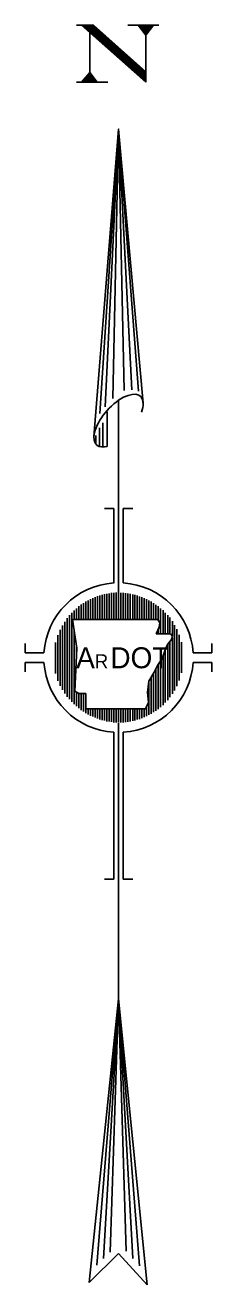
# Model space of a CAD drawing. Extents: x -0.25 to 1.92, y 0 to 0.95.
# Drawn here: x 1.6158 to 1.6401, y 0.2614 to 0.4252 of the extents above; entities that cross this region are included whole.
import ezdxf

# ---------------------------------------------------------------- set-up
doc = ezdxf.new("R2010")
doc.units = 0
doc.layers.add('SHET_Border-Text', color=7, linetype='Continuous')

msp = doc.modelspace()

# ---------------------------------------------------------------- linework, layer by layer
at = {"layer": 'SHET_Border-Text'}
for p, q in [((1.6224669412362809, 0.42522347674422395), (1.6246832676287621, 0.42522347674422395)), ((1.623141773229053, 0.42522347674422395), (1.6314915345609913, 0.41780460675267)), ((1.6232376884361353, 0.42522347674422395), (1.6314915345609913, 0.4179013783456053)), ((1.6233344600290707, 0.42522347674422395), (1.6314915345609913, 0.4179656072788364)), ((1.6234303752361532, 0.42522347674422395), (1.6314915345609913, 0.418061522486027)), ((1.6235271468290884, 0.42522347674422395), (1.6314915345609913, 0.41812575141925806)), ((1.623623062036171, 0.42522347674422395), (1.6314915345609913, 0.41822252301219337)), ((1.6236872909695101, 0.42522347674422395), (1.6314915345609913, 0.4182867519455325)), ((1.623784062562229, 0.42522347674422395), (1.6314915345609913, 0.418382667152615)), ((1.6238799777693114, 0.42522347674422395), (1.6314915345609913, 0.4184468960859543)), ((1.6239767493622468, 0.42522347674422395), (1.6314915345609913, 0.41854366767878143)), ((1.6240726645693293, 0.42522347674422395), (1.6314915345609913, 0.4186395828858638)), ((1.6241694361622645, 0.42522347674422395), (1.6314915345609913, 0.4187038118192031)), ((1.6242011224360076, 0.42522347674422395), (1.6242011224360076, 0.41780460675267)), ((1.624265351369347, 0.42522347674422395), (1.6314915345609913, 0.4188005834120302)), ((1.6243295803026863, 0.42522347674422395), (1.6314915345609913, 0.4188648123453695)), ((1.6244263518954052, 0.42522347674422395), (1.6314915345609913, 0.41896072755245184)), ((1.6245222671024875, 0.42522347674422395), (1.6314915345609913, 0.41902495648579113)), ((1.6246190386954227, 0.42522347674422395), (1.6314915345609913, 0.41912172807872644)), ((1.6246832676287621, 0.42522347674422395), (1.6314915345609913, 0.4191534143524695)), ((1.6310093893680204, 0.42522347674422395), (1.6291467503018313, 0.42522347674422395)), ((1.6331931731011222, 0.42522347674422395), (1.6310093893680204, 0.42522347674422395)), ((1.6314915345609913, 0.42522347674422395), (1.6314915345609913, 0.41780460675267)), ((1.6224669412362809, 0.41780460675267), (1.6246832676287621, 0.41780460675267)), ((1.6246832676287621, 0.41780460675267), (1.6265459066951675, 0.41780460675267)), ((1.6279589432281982, 0.351488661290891), (1.6279589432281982, 0.37640948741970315)), ((1.6259036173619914, 0.3704361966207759), (1.6259036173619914, 0.3735191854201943)), ((1.6264816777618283, 0.3704361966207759), (1.6264816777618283, 0.37496390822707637)), ((1.6249718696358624, 0.3709174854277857), (1.6249718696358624, 0.37188091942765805)), ((1.6254540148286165, 0.3705321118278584), (1.6254540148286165, 0.37284435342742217)), ((1.626127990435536, 0.3623750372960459), (1.6273483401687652, 0.3623750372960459)), ((1.6273483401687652, 0.35267646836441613), (1.6273483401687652, 0.3623750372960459)), ((1.6285686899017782, 0.3527090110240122), (1.6285686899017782, 0.3623750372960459)), ((1.6285686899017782, 0.3623750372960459), (1.6297890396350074, 0.3623750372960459)), ((1.624297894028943, 0.34795606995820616), (1.624297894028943, 0.35058945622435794)), ((1.6246190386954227, 0.34795606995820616), (1.6246190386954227, 0.3507179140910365)), ((1.624907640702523, 0.34795606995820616), (1.624907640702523, 0.35084637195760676)), ((1.6251970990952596, 0.34795606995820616), (1.6251970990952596, 0.35097482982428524)), ((1.6255182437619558, 0.34795606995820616), (1.6255182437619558, 0.3510707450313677)), ((1.625806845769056, 0.34795606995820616), (1.625806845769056, 0.3511675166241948)), ((1.626127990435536, 0.34795606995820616), (1.626127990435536, 0.35123174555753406)), ((1.6264174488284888, 0.34795606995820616), (1.6264174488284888, 0.3512959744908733)), ((1.6267385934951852, 0.34795606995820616), (1.6267385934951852, 0.3513276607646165)), ((1.627027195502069, 0.34795606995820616), (1.627027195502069, 0.35139188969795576)), ((1.6273483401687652, 0.34795606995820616), (1.6273483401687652, 0.3514244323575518)), ((1.627637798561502, 0.34795606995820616), (1.627637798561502, 0.351456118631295)), ((1.6279589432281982, 0.34795606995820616), (1.6279589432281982, 0.351488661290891)), ((1.6282475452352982, 0.34795606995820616), (1.6282475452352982, 0.3514244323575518)), ((1.6285686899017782, 0.34795606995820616), (1.6285686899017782, 0.3514244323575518)), ((1.6288581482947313, 0.34795606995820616), (1.6288581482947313, 0.35136020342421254)), ((1.6291792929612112, 0.34795606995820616), (1.6291792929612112, 0.3513276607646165)), ((1.6294678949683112, 0.34795606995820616), (1.6294678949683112, 0.3512634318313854)), ((1.6297890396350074, 0.34795606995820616), (1.6297890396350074, 0.3511992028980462)), ((1.6300784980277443, 0.34795606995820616), (1.6300784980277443, 0.35113497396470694)), ((1.6303671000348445, 0.34795606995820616), (1.6303671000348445, 0.3510390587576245)), ((1.6306882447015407, 0.34795606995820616), (1.6306882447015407, 0.35094228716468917)), ((1.6309777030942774, 0.34795606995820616), (1.6309777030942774, 0.35084637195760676)), ((1.6312988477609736, 0.34795606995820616), (1.6312988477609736, 0.3507179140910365)), ((1.6315874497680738, 0.34795606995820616), (1.6315874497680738, 0.35058945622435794)), ((1.6221783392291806, 0.34795606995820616), (1.6221783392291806, 0.349112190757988)), ((1.6224669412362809, 0.34795606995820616), (1.6224669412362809, 0.3493691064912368)), ((1.622788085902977, 0.34795606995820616), (1.622788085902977, 0.349657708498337)), ((1.6230775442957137, 0.34795606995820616), (1.6230775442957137, 0.34988293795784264)), ((1.62339868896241, 0.34795606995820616), (1.62339868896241, 0.3500756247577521)), ((1.6236872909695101, 0.34795606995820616), (1.6236872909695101, 0.35026831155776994)), ((1.62400843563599, 0.34795606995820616), (1.62400843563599, 0.35042845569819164)), ((1.6319085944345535, 0.34795606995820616), (1.6319085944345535, 0.35042845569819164)), ((1.6321980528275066, 0.34795606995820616), (1.6321980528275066, 0.35026831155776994)), ((1.6325191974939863, 0.34795606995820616), (1.6325191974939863, 0.3500756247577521)), ((1.6328077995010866, 0.34795606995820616), (1.6328077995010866, 0.3498503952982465)), ((1.633128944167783, 0.3478918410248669), (1.633128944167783, 0.349657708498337)), ((1.6334184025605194, 0.3461251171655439), (1.6334184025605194, 0.3493691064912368)), ((1.6337395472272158, 0.3461251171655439), (1.6337395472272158, 0.3491438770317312)), ((1.6209579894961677, 0.33832172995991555), (1.6209579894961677, 0.34763492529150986)), ((1.6212465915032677, 0.337872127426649), (1.6212465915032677, 0.3481162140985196)), ((1.6215677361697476, 0.33758266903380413), (1.6215677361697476, 0.3485015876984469)), ((1.6218571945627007, 0.33722983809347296), (1.6218571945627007, 0.3487910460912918)), ((1.62253117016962, 0.3442307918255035), (1.621953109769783, 0.34795606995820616)), ((1.621953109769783, 0.34795606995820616), (1.6330647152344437, 0.34795606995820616)), ((1.6330647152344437, 0.34795606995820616), (1.6330647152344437, 0.34795606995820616)), ((1.6330647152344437, 0.34795606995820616), (1.6333216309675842, 0.3475064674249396)), ((1.6333216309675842, 0.3475064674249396), (1.6332574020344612, 0.3469600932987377)), ((1.634028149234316, 0.3461251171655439), (1.634028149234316, 0.34882273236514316)), ((1.6343492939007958, 0.3460934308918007), (1.6343492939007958, 0.3485015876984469)), ((1.6346387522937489, 0.3460934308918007), (1.6346387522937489, 0.34818044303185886)), ((1.6349598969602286, 0.34586820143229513), (1.6349598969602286, 0.3477308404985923)), ((1.6200262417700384, 0.33995913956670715), (1.6200262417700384, 0.34590074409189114)), ((1.6203473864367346, 0.3393168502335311), (1.6203473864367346, 0.3466072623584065)), ((1.6206368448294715, 0.3388030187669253), (1.6206368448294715, 0.3471527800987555)), ((1.6221783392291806, 0.33690869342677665), (1.6221783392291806, 0.3464145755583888)), ((1.6332574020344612, 0.3469600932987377), (1.6328403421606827, 0.3460934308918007)), ((1.6328403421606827, 0.3460934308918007), (1.6347346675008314, 0.3460934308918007)), ((1.633128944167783, 0.3460934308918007), (1.633128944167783, 0.3466389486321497)), ((1.6347346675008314, 0.3460934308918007), (1.6349915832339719, 0.34577228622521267)), ((1.6349915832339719, 0.34577228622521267), (1.6348631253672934, 0.3453543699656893)), ((1.6352484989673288, 0.33870710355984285), (1.6352484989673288, 0.34721700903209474)), ((1.6355379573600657, 0.33928516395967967), (1.6355379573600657, 0.34667149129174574)), ((1.6358591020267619, 0.33999168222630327), (1.6358591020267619, 0.3459649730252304)), ((1.61578713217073, 0.3435885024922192), (1.61578713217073, 0.3448088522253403)), ((1.6197376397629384, 0.3409225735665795), (1.6197376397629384, 0.344968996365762)), ((1.622274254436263, 0.33861033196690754), (1.62253117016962, 0.3442307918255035)), ((1.6224669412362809, 0.34355595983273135), (1.6224669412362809, 0.3443909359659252)), ((1.6339964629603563, 0.3438771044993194), (1.6343176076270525, 0.34468039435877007)), ((1.6348631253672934, 0.3453543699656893), (1.6343176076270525, 0.34468039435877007)), ((1.6343492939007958, 0.33745421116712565), (1.6343492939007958, 0.34468039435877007)), ((1.6346387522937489, 0.33783958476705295), (1.6346387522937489, 0.34506576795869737)), ((1.6349598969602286, 0.3382575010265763), (1.6349598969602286, 0.345547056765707)), ((1.636147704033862, 0.34101934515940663), (1.636147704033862, 0.3450015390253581)), ((1.6400982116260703, 0.3435885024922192), (1.6400982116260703, 0.3448088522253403)), ((1.61578713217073, 0.3435885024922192), (1.6182366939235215, 0.3435885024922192)), ((1.61578713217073, 0.3411478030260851), (1.61578713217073, 0.3423681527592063)), ((1.61578713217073, 0.3423681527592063), (1.6182370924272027, 0.3423681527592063)), ((1.6336427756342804, 0.3428819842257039), (1.6330004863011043, 0.3419502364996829)), ((1.6334184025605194, 0.33655500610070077), (1.6334184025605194, 0.3424966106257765)), ((1.6339964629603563, 0.3438771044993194), (1.6336427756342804, 0.3428819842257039)), ((1.6337395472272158, 0.3368119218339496), (1.6337395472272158, 0.34310635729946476)), ((1.634028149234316, 0.3371330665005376), (1.634028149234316, 0.3439096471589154)), ((1.637661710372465, 0.3423681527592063), (1.6400982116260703, 0.3423681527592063)), ((1.6376621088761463, 0.3435885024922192), (1.6400982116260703, 0.3435885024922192)), ((1.6400982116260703, 0.3423681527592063), (1.6400982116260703, 0.3411478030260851)), ((1.6325834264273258, 0.34108357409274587), (1.6319085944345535, 0.33992745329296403)), ((1.6325191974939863, 0.3358810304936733), (1.6325191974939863, 0.3408583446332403)), ((1.6330004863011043, 0.3419502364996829), (1.6325834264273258, 0.34108357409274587)), ((1.6328077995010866, 0.3360737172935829), (1.6328077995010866, 0.34146894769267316)), ((1.633128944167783, 0.3362980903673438), (1.633128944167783, 0.34204700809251)), ((1.6319085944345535, 0.33992745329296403), (1.6317159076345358, 0.3384501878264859)), ((1.6319085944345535, 0.3355273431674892), (1.6319085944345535, 0.33967053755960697)), ((1.6321980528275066, 0.3356883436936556), (1.6321980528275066, 0.3403128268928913)), ((1.6227563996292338, 0.33832172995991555), (1.622274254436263, 0.33861033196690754)), ((1.6224669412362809, 0.3366517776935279), (1.6224669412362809, 0.3384501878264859)), ((1.6236872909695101, 0.33832172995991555), (1.6227563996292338, 0.33832172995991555)), ((1.622788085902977, 0.33639486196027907), (1.622788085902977, 0.3382891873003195)), ((1.6230775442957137, 0.3361379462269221), (1.6230775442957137, 0.3382891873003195)), ((1.62339868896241, 0.33597694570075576), (1.62339868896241, 0.3382891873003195)), ((1.6236872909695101, 0.33633063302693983), (1.6236872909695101, 0.33832172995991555)), ((1.6317159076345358, 0.3384501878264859), (1.6318443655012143, 0.3371330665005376)), ((1.631458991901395, 0.33633063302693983), (1.6236872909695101, 0.33633063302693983)), ((1.6236872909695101, 0.3357525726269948), (1.6236872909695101, 0.3362980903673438)), ((1.62400843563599, 0.33559157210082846), (1.62400843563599, 0.33633063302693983)), ((1.624297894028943, 0.33543142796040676), (1.624297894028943, 0.33633063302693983)), ((1.6246190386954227, 0.3353029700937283), (1.6246190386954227, 0.33633063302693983)), ((1.624907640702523, 0.33517451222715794), (1.624907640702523, 0.33633063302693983)), ((1.6251970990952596, 0.33504605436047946), (1.6251970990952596, 0.33633063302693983)), ((1.6255182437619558, 0.33494928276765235), (1.6255182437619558, 0.33633063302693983)), ((1.625806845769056, 0.3348533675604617), (1.625806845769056, 0.33633063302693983)), ((1.626127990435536, 0.3347891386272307), (1.626127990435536, 0.33633063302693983)), ((1.6264174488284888, 0.33469236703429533), (1.6264174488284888, 0.33633063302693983)), ((1.6267385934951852, 0.33466068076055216), (1.6267385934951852, 0.33633063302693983)), ((1.627027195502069, 0.3346281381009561), (1.627027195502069, 0.33633063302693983)), ((1.6273483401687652, 0.33456390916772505), (1.6273483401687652, 0.33633063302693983)), ((1.627637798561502, 0.33453222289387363), (1.627637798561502, 0.33633063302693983)), ((1.6279589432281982, 0.33453222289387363), (1.6279589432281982, 0.33633063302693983)), ((1.6282475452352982, 0.33453222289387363), (1.6282475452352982, 0.33633063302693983)), ((1.6285686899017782, 0.33456390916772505), (1.6285686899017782, 0.33633063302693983)), ((1.6288581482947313, 0.33459645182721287), (1.6288581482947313, 0.33633063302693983)), ((1.6291792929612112, 0.3346281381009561), (1.6291792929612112, 0.33633063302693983)), ((1.6294678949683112, 0.33469236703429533), (1.6294678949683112, 0.33633063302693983)), ((1.6297890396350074, 0.3347565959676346), (1.6297890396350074, 0.33633063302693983)), ((1.6300784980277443, 0.3348208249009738), (1.6300784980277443, 0.33633063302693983)), ((1.6303671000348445, 0.33491759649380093), (1.6303671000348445, 0.33633063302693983)), ((1.6306882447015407, 0.3349818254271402), (1.6306882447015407, 0.33633063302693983)), ((1.6309777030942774, 0.3351102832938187), (1.6309777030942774, 0.33633063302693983)), ((1.6312988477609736, 0.335238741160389), (1.6312988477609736, 0.33633063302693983)), ((1.6318443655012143, 0.3371330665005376), (1.631458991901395, 0.33633063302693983)), ((1.6315874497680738, 0.3353671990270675), (1.6315874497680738, 0.33649077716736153)), ((1.6279589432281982, 0.29859570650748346), (1.6279589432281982, 0.3344679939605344)), ((1.6273483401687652, 0.3141716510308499), (1.6273483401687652, 0.3332793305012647)), ((1.6285686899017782, 0.3141716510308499), (1.6285686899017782, 0.3332793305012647)), ((1.626127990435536, 0.3141716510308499), (1.6273483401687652, 0.3141716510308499)), ((1.6285686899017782, 0.3141716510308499), (1.6297890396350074, 0.3141716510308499)), ((1.6279589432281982, 0.29859570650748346), (1.624123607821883, 0.2617028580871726)), ((1.6316658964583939, 0.26142069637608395), (1.6279589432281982, 0.29859570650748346)), ((1.624123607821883, 0.2617028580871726), (1.6279589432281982, 0.2655109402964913)), ((1.6279589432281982, 0.2655109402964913), (1.6316658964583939, 0.26142069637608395))]:
    msp.add_line(p, q, dxfattribs=at)
for points in [[(1.6325191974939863, 0.42522347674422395), (1.6314915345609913, 0.4239388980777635), (1.6304955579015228, 0.42522347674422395), (1.6306565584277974, 0.42515924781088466), (1.632390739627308, 0.42515924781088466), (1.6314915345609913, 0.4240348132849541), (1.6306882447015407, 0.4250950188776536), (1.632293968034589, 0.42512670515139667), (1.6314915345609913, 0.42416327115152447), (1.6308167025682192, 0.4250307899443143), (1.6321338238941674, 0.42506247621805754), (1.6314915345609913, 0.42426004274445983), (1.6309451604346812, 0.424966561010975), (1.631972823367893, 0.42499824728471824), (1.6314915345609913, 0.42438850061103), (1.6311061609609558, 0.4249023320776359), (1.6318443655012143, 0.424934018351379), (1.6314915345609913, 0.4244844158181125), (1.6312346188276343, 0.4248381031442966), (1.6316842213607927, 0.4248697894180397), (1.6314915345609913, 0.4245811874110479), (1.6313630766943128, 0.4248055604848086), (1.631555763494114, 0.4248055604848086), (1.6314915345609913, 0.42467710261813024), (1.631458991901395, 0.4247738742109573), (1.6314915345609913, 0.4247738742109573)], [(1.623141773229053, 0.41780460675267), (1.6242011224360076, 0.41908918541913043), (1.62516455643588, 0.41780460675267), (1.6250360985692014, 0.4178688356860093), (1.6232702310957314, 0.4178688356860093), (1.6241694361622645, 0.41899327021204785), (1.6250044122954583, 0.4179330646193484), (1.62339868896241, 0.4179013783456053), (1.6241694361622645, 0.4188648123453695), (1.6248759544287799, 0.4179972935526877), (1.6235271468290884, 0.4179656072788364), (1.6241694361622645, 0.41876804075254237), (1.6247149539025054, 0.418061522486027), (1.6237198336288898, 0.4180298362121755), (1.6242011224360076, 0.4186721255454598), (1.6245548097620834, 0.41812575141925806), (1.6238482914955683, 0.4180940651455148), (1.6241694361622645, 0.41854366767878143), (1.6244263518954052, 0.41818998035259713), (1.6239767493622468, 0.4181582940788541), (1.6241694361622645, 0.4184468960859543), (1.624297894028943, 0.41822252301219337), (1.6241052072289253, 0.41822252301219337), (1.6241694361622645, 0.41835098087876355), (1.6242336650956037, 0.41825420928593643), (1.6242011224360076, 0.41825420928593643)], [(1.6247474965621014, 0.3716882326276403), (1.6279589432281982, 0.4117028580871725), (1.631170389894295, 0.37605580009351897)], [(1.6255182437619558, 0.37473953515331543), (1.6279589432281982, 0.4117028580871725), (1.630528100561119, 0.3776298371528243)], [(1.6261922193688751, 0.37560619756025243), (1.6279589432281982, 0.4117028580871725), (1.6296605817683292, 0.3778225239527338)], [(1.6271881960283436, 0.3766664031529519), (1.6279589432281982, 0.4117028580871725), (1.6286971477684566, 0.37772575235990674)], [(1.6251339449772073, 0.2639949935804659), (1.6279589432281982, 0.29859570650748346), (1.630656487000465, 0.2638824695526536)], [(1.6298081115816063, 0.26483084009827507), (1.6279589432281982, 0.29859570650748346), (1.6259864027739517, 0.2648444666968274)], [(1.6268382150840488, 0.2656622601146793), (1.6279589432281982, 0.29859570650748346), (1.6289280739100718, 0.2657807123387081)]]:
    msp.add_lwpolyline(points, dxfattribs=at)
for start, end in [(93.60728333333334, 176.423906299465), (3.576093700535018, 86.41458888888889), (183.61351343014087, 266.41232777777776), (273.5988916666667, 356.38648656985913)]:
    msp.add_arc((1.627949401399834, 0.34298149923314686), 0.009731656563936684, start, end, dxfattribs=at)
for start_param, end_param in [(2.6816372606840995, 5.778781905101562), (2.29250568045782, 2.6778136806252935), (5.778781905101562, 6.897373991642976)]:
    msp.add_ellipse((1.627949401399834, 0.37380377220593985), major_axis=(-0.0028488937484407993, -0.0031640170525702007), ratio=0.4675851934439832, start_param=start_param, end_param=end_param, dxfattribs=at)

# ---------------------------------------------------------------- texts
for s, height, p in [('A  DOT', 0.0027233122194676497, (1.6224327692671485, 0.3415997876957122)), ('R', 0.0018155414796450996, (1.6248469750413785, 0.34159979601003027))]:
    msp.add_text(s, height=height, dxfattribs=at).set_placement(p)

doc.saveas('drawing.dxf')
